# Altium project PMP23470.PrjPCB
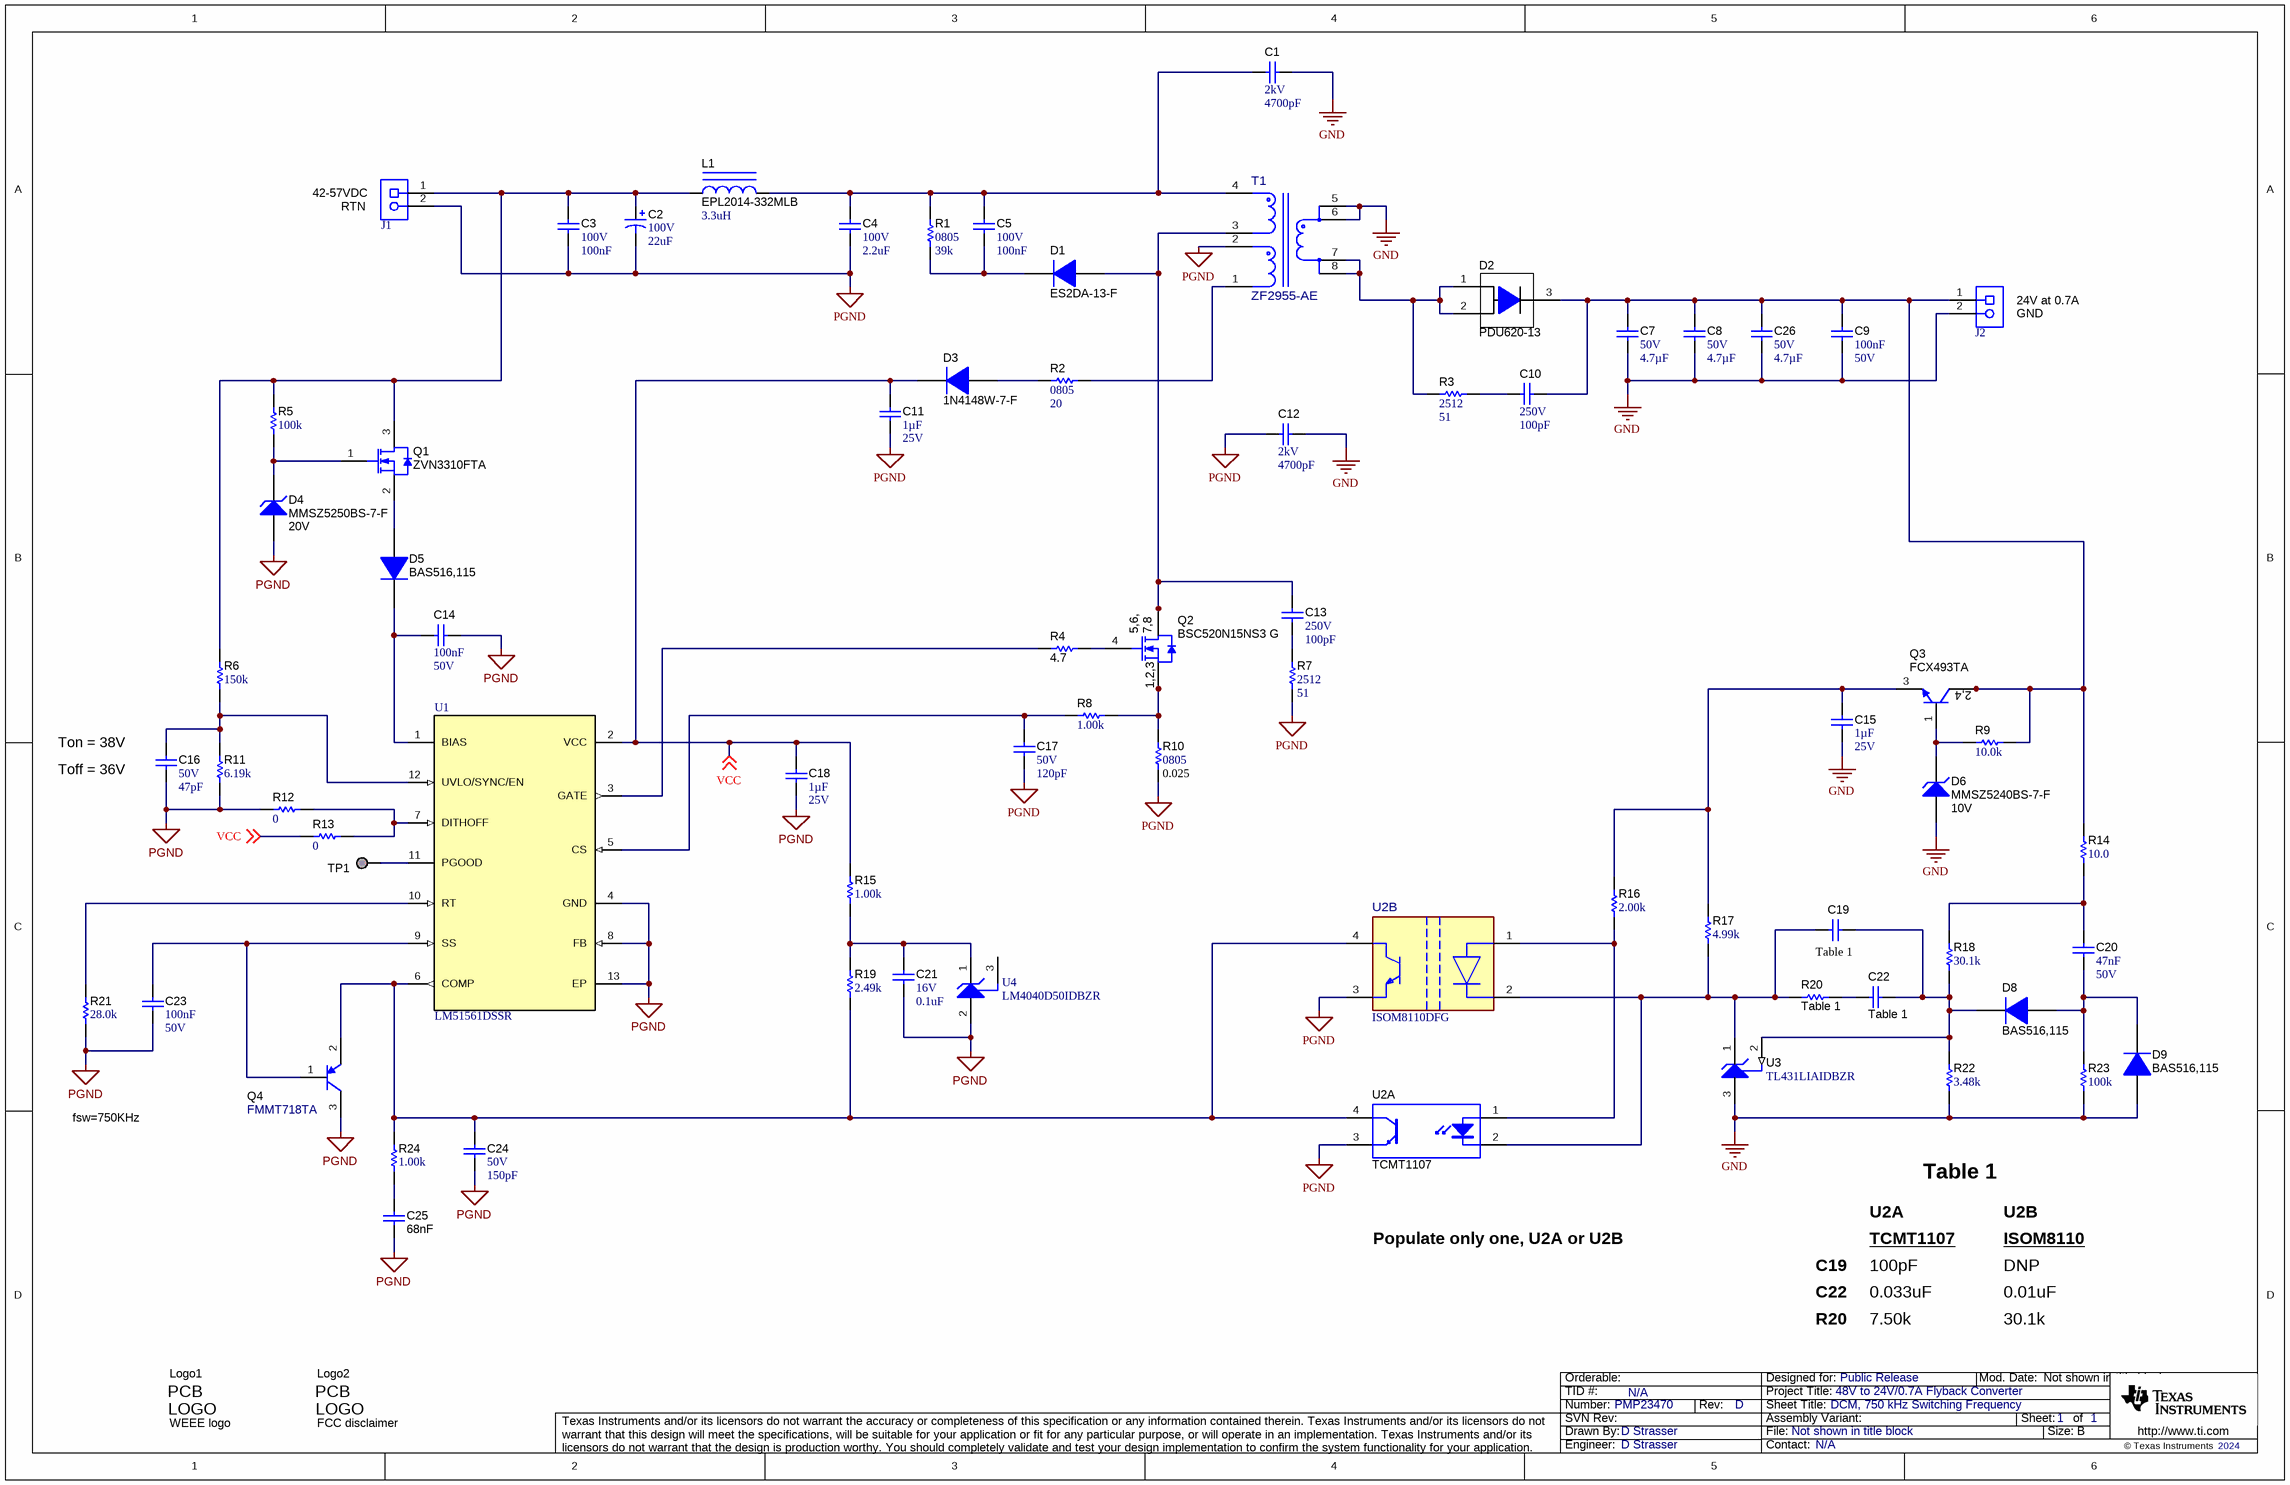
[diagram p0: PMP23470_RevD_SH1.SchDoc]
CopyrightYear: 2024; PCB_Layout: D Strasser; PCB_Rev: D; PRJ_Customer: Public Release; PRJ_Engineer: D Strasser; PRJ_Number: PMP23470; PRJ_Title: 48V to 24V/0.7A Flyback Converter; SCH_Rev: D; TechSupport: N/A; TID: N/A
1 sheet, 73 parts. Net scope: global (net labels, ports and power ports of the same name join across sheets).
Board file: PMP23470_RevD.PcbDoc

## Sheet PMP23470_RevD_SH1.SchDoc: DCM, 750 kHz Switching Frequency
size 431 x 279 mm; Date: Not shown in title block; ApprovedBy: Not shown in title block; CheckedBy: Not shown in title block; Author: Not shown in title block; CompanyName: Not shown in title block; DrawnBy: D Strasser; Engineer: Not shown in title block; Organization: Not shown in title block; Address1: Not shown in title block; Address2: Not shown in title block; Address3: Not shown in title block; Address4: Not shown in title block; DocumentNumber: 1; Revision: Use project parameter SCH_Rev; SheetNumber: 1; SheetTotal: 1; PageSetup: Record=PageOptions¦CenterHorizontal=True¦CenterVertical=True¦PrintScale=1.00¦XCorrection=1.00¦YCorrection=1.00¦PrintKind=0¦BorderSize=5000000¦LeftOffset=0¦BottomOffset=0¦Orientation=2¦PaperLength=1000¦PaperWidth=1000¦Scale=100¦PaperSource=15¦PrintQuality=600¦MediaType=1¦DitherType=10¦PaperKind=Letter¦PrintScaleMode=1

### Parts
C1  VDC_V: 2kV  ValueDisplayed: 4700pF  [1812_HV]  (hidden comment: 1812GC472KA1)
C2  VDC_V: 100V  ValueDisplayed: 22uF  [SM_RADIAL_F]  (hidden comment: EEE-FK2A220P)
C3  VDC_V: 100V  Cap_F: 100nF  [0805_HV1]  (hidden comment: 885012207128)
C4  VDC_V: 100V  ValueDisplayed: 2.2uF  [1210_210L]  (hidden comment: C1210C225K1RAC7800)
C5  VDC_V: 100V  Cap_F: 100nF  [0805_HV1]  (hidden comment: 885012207128)
C7  VDC_V: 50V  ValueDisplayed: 4.7µF  [1210_280]  (hidden comment: C1210C475K5RACAUTO)
C8  VDC_V: 50V  ValueDisplayed: 4.7µF  [1210_280]  (hidden comment: C1210C475K5RACAUTO)
C9  Cap_F: 100nF  VDC_V: 50V  [0603L]  (hidden comment: C0603C104K5RACTU)
C10  VDC_V: 250V  ValueDisplayed: 100pF  [0805_HV1]  (hidden comment: GRM21A5C2E101JW01D)
C11  Cap_F: 1µF  VDC_V: 25V  [0603L]  (hidden comment: C0603C105K3RACTU)
C12  VDC_V: 2kV  ValueDisplayed: 4700pF  [1812_HV]  (hidden comment: 1812GC472KA1)
C13  VDC_V: 250V  ValueDisplayed: 100pF  [0805_HV1]  (hidden comment: GRM21A5C2E101JW01D)
C14  Cap_F: 100nF  VDC_V: 50V  [0603L]  (hidden comment: C0603C104K5RACTU)
C15  Cap_F: 1µF  VDC_V: 25V  [0603L]  (hidden comment: C0603C105K3RACTU)
C16  VDC_V: 50V  ValueDisplayed: 47pF  [0402L]  (hidden comment: 885012005044)
C17  VDC_V: 50V  ValueDisplayed: 120pF  [0402L]  (hidden comment: GRM1555C1H121JA01D)
C18  Cap_F: 1µF  VDC_V: 25V  [0603L]  (hidden comment: C0603C105K3RACTU)
C19  Table 1  [0402L]  (value not drawn)
C20  Cap_F: 47nF  VDC_V: 50V  [0603L]  (hidden comment: C1608X7R1H473K080AA)
C21  VDC_V: 16V  ValueDisplayed: 0.1uF  [0402L]  (hidden comment: 885012205037)
C22  Table 1  [0603L]
C23  Cap_F: 100nF  VDC_V: 50V  [0603L]  (hidden comment: C0603C104K5RACTU)
C24  VDC_V: 50V  ValueDisplayed: 150pF  [0402L]  (hidden comment: 885012005062)
C25  Cap_F: 68nF  [0603L]  (hidden comment: 885012206070)
C26  VDC_V: 50V  ValueDisplayed: 4.7µF  [1210_280]  (hidden comment: C1210C475K5RACAUTO)
D1  ES2DA-13-F  [SMA]
D2  PDU620-13  [POWERDI5]
D3  1N4148W-7-F  [SOD-123]
D4  MMSZ5250BS-7-F  value 20V  [SOD-323]
D5  BAS516,115  [SOD-523]
D6  MMSZ5240BS-7-F  value 10V  [SOD-323]
D8  BAS516,115  [SOD-523]
D9  BAS516,115  [SOD-523]
J1  ED555/2DS  [TERM_BLK_ED555-2DS]  (value not drawn)
J2  ED555/2DS  [TERM_BLK_ED555-2DS]  (value not drawn)
L1  EPL2014-332MLB  ValueDisplayed: 3.3uH  [EPL2014]
Logo1  WEEE logo  [WEEE_Minimum]  (no BOM)
Logo2  FCC disclaimer  [FCC_disclaimer]  (no BOM)
Q1  ZVN3310FTA  [SOT-23]
Q2  BSC520N15NS3 G  [PG-TDSON-8]
Q3  FCX493TA  [SOT-89-3]
Q4  FMMT718TA  [SOT-23L]
R1  PackageReference: 0805  ValueDisplayed: 39k  [0805_HV]  (hidden comment: CRCW080539K0JNEA)
R2  PackageReference: 0805  ValueDisplayed: 20  [0805_HV]  (hidden comment: ERJ-6GEYJ200V)
R3  ValueDisplayed: 51  [2512]  (hidden comment: CRCW251251R0JNEG)
R4  ValueDisplayed: 4.7  [0402L]  (hidden comment: CRCW04024R70JNED)
R5  ValueDisplayed: 100k  [0402L]  (hidden comment: CRCW0402100KFKED)
R6  ValueDisplayed: 150k  [0402L]  (hidden comment: CRCW0402150KFKED)
R7  ValueDisplayed: 51  [2512]  (hidden comment: CRCW251251R0JNEG)
R8  ValueDisplayed: 1.00k  [0402L]  (hidden comment: CRCW04021K00FKED)
R9  ValueDisplayed: 10.0k  [0402L]  (hidden comment: CRCW040210K0FKED)
R10  PackageReference: 0805  ValueDisplayed: 0.025  [WSL0805]  (hidden comment: WSL0805R0250FEA)
R11  ValueDisplayed: 6.19k  [0402L]  (hidden comment: CRCW04026K19FKED)
R12  ValueDisplayed: 0  [0402L]  (hidden comment: CRCW04020000Z0ED)
R13  ValueDisplayed: 0  [0402L]  (hidden comment: CRCW04020000Z0ED)
R14  ValueDisplayed: 10.0  [0402L]  (hidden comment: CRCW040210R0FKED)
R15  ValueDisplayed: 1.00k  [0402L]  (hidden comment: CRCW04021K00FKED)
R16  ValueDisplayed: 2.00k  [0402L]  (hidden comment: CRCW04022K00FKED)
R17  ValueDisplayed: 4.99k  [0402L]  (hidden comment: CRCW04024K99FKED)
R18  ValueDisplayed: 30.1k  [0402L]  (hidden comment: CRCW040230K1FKED)
R19  ValueDisplayed: 2.49k  [0402L]  (hidden comment: CRCW04022K49FKED)
R20  Table 1  [0402L]
R21  ValueDisplayed: 28.0k  [0402L]  (hidden comment: CRCW040228K0FKED)
R22  ValueDisplayed: 3.48k  [0402L]  (hidden comment: CRCW04023K48FKED)
R23  ValueDisplayed: 100k  [0402L]  (hidden comment: CRCW0402100KFKED)
R24  ValueDisplayed: 1.00k  [0402L]  (hidden comment: CRCW04021K00FKED)
T1  ZF2955-AE  [FP-ZF2955-AE_SMT_XFRMR_13MM2_10MM9-MFG]
TP1  TP_SM_1MM  [TP_SM_1MM]  (value not drawn)  (no BOM)
U1  LM51561DSSR  [DSS0012B]
U2A  TCMT1107  [SOP-4]
U2B  ISOM8110DFG  [DFG0004A-MFG]
U3  TL431LIAIDBZR  [DBZ0003A_L]
U4  LM4040D50IDBZR  [DBZ0003A_N]

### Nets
GND: C1.1 C7.1 C8.1 C9.2 C12.1 C15.1 C26.1 D6.2(A) D9.2(A) J2.2 R22.2 R23.2 T1.5 T1.6 U3.3(ANODE)
PGND: C2.2(-) C3.1 C4.1 C11.1 C12.2 C14.1 C16.1 C17.1 C18.1 C21.2 C23.2 C24.2 C25.1 D4.2(A) J1.2 Q4.3(C) R7.2 R10.2 R11.2 R12.1 R21.2 T1.2 U1.4(GND) U1.8(FB) U1.13(EP) U2A.3(E) U2B.3(Emitter) U4.2(ANODE)
VCC: C11.2 C18.2 D3.1(K) R13.1 R15.1 U1.2(VCC) ; off-sheet VCC
NetC1_2: C1.2 C4.2 C5.2 L1.2 R1.1 T1.4
NetC2_1: C2.1(+) C3.2 J1.1 L1.1 Q1.3(D) R5.1 R6.1
NetC5_1: C5.1 D1.1(K) R1.2
NetC7_2: C7.2 C8.2 C9.1 C10.2 C26.2 D2.3(K) J2.1 Q3.2(C) Q3.4(C) R9.2 R14.1
NetC10_1: C10.1 R3.2
NetC13_1: C13.1 R7.1
NetC13_2: C13.2 D1.2(A) Q2.5(D) Q2.6(D) Q2.7(D) Q2.8(D) Q2.9(D) T1.3
NetC14_2: C14.2 D5.1(K) U1.1(BIAS)
NetC15_2: C15.2 Q3.3(E) R16.1 R17.1
NetC16_2: C16.2 R6.2 R11.1 U1.12(UVLO/SYNC/EN)
NetC17_2: C17.2 R8.2 U1.5(CS)
NetC19_1: C19.1 C22.1 D8.1(K) R18.2 R22.1 U3.2(REF)
NetC19_2: C19.2 R17.2 R20.1 U2A.2(K) U2B.2(CAT) U3.1(CATHODE)
NetC20_1: C20.1 D8.2(A) D9.1(K) R23.1
NetC20_2: C20.2 R14.2 R18.1
NetC21_1: C21.1 R15.2 R19.1 U4.1(CATHODE)
NetC22_2: C22.2 R20.2
NetC23_1: C23.1 Q4.1(B) U1.9(SS)
NetC24_1: C24.1 Q4.2(E) R19.2 R24.1 U1.6(COMP) U2A.4(C) U2B.4(Collector)
NetC25_2: C25.2 R24.2
NetD2_1: D2.1(A) D2.2(A) R3.1 T1.7 T1.8
NetD3_2: D3.2(A) R2.1
NetD4_1: D4.1(K) Q1.1(G) R5.2
NetD5_2: D5.2(A) Q1.2(S)
NetD6_1: D6.1(K) Q3.1(B) R9.1
NetQ2_1: Q2.1(S) Q2.2(S) Q2.3(S) R8.1 R10.1
NetQ2_4: Q2.4(G) R4.1
NetR2_2: R2.2 T1.1
NetR4_2: R4.2 U1.3(GATE)
NetR12_2: R12.2 R13.2 U1.7(DITHOFF)
NetR16_2: R16.2 U2A.1(A) U2B.1(AN)
NetR21_1: R21.1 U1.10(RT)
NetTP1_1: TP1.1 U1.11(PGOOD)

Not connected (* = marked no-connect by the designer): U4 3(NC)

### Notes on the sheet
- (near J1) 42-57VDC
- (near J1) RTN
- (near J2) 24V at 0.7A
- (near J2) GND
- (near C16) Ton = 38V
- (near C16) Toff = 36V
- (near C19) Table 1
- fsw=750KHz
- Table 1
- Populate only one, U2A or U2B
- TCMT1107
- U2A
- ISOM8110
- U2B
- C19
- C22
- 100pF
- 0.033uF
- DNP
- 0.01uF
- R20
- 7.50k
- 30.1k

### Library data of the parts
C1 C12 = CMP-0009294-2: CAP, CERM, 4700 pF, 2000 V, +/- 10%, X7R, 1812; Manufacturer: AVX; TaMin_C: -55°C; Polarized: N; SizeAreaWB_mm2: 23.1; Value1: Unknown; U/M: EA; Value: 4700pF; TaMax_C: 125°C; SizeZ_mm: 1.35; SizeX_mm: 4.5; SizeY_mm: 3.2; Cap_Case: 1812; Value2: 2000V; SizeArea_mm2: 14.4; Cap_F: 4.7nF; AEC Category: Q200
C2 = CMP-0011202-2: CAP, AL, 22 uF, 100 V, +/- 20%, 1.3 ohm, AEC-Q200 Grade 2, SMD; Manufacturer: Panasonic; TaMin_C: -55°C; ESR_ohm: 1.3; Polarized: Y; SizeAreaWB_mm2: 123.6; Value1: 1.3 ohm; U/M: EA; Value: 22uF; TaMax_C: 105°C; SizeZ_mm: 10.2; SizeX_mm: 10; SizeY_mm: 8.3; Cap_Case: F; SizeArea_mm2: 83; CompType: Capacitor; Cap_F: 22µF; IRMS_A: 130mA; AEC Grade: 2; AEC Category: Q200
C3 C5 = CMP-0750058-1: CAP, CERM, 0.1 µF, 100 V,+/- 10%, X7R, 0805; Manufacturer: Wurth Elektronik; TaMin_C: -55°C; AEC Category: Q200; U/M: EA; SizeY_mm: 1.25; Polarized: N; Value: 0.1uF; SizeX_mm: 2; TaMax_C: 125°C; ValueDisplayed: 0.1µF; SizeArea_mm2: 2.5; Cap_Case: 0805; SizeZ_mm: 1.45; SizeAreaWB_mm2: 6.75
C4 = CMP-0009084-2: CAP, CERM, 2.2 uF, 100 V, +/- 10%, X7R, 1210; Manufacturer: Kemet; TaMin_C: -55°C; Polarized: N; SizeAreaWB_mm2: 14.7; Value1: Unknown; U/M: EA; Value: 2.2uF; TaMax_C: 125°C; SizeZ_mm: 2.1; SizeX_mm: 3.2; SizeY_mm: 2.5; Cap_Case: 1210; SizeArea_mm2: 8; Cap_F: 2.2µF; AEC Category: Q200
C7 C8 C26 = CMP-0079604-1: CAP, CERM, 4.7 µF, 50 V,+/- 10%, X7R, AEC-Q200 Grade 1, 1210; Manufacturer: Kemet; TaMin_C: -55°C; Polarized: N; SizeAreaWB_mm2: 14.7; U/M: EA; Value: 4.7uF; TaMax_C: 125°C; SizeZ_mm: 2.8; SizeX_mm: 3.2; SizeY_mm: 2.5; Cap_Case: 1210; SizeArea_mm2: 8; AEC Qualified: Y; AEC Grade: 1; AEC Category: Q200
C9 C14 C23 = CMP-0006861-4: CAP, CERM, 0.1 uF, 50 V, +/- 10%, X7R, 0603; Manufacturer: Kemet; TaMin_C: -55°C; Polarized: N; SizeAreaWB_mm2: 4.68; Value1: Unknown; U/M: EA; Value: 0.1uF; TaMax_C: 125°C; SizeZ_mm: 1; SizeX_mm: 1.6; SizeY_mm: 0.8; Cap_Case: 0603; SizeArea_mm2: 1.28; AEC Category: Q200
C10 C13 = CMP-0008236-2: CAP, CERM, 100 pF, 250 V, +/- 5%, C0G/NP0, 0805; Manufacturer: MuRata; TaMin_C: -55°C; Polarized: N; SizeAreaWB_mm2: 6.75; Value1: Unknown; U/M: EA; Value: 100pF; TaMax_C: 125°C; SizeZ_mm: 1.45; SizeX_mm: 2; SizeY_mm: 1.25; Cap_Case: 0805; SizeArea_mm2: 2.5; AEC Category: Q200
C11 C15 C18 = CMP-0006867-4: CAP, CERM, 1 uF, 25 V, +/- 10%, X7R, 0603; Manufacturer: Kemet; TaMin_C: -55°C; Polarized: N; SizeAreaWB_mm2: 4.68; Value1: Unknown; U/M: EA; Value: 1uF; TaMax_C: 125°C; SizeZ_mm: 1; SizeX_mm: 1.6; SizeY_mm: 0.8; Cap_Case: 0603; SizeArea_mm2: 1.28; AEC Category: Q200
C16 = CMP-0006214-2: CAP, CERM, 47 pF, 50 V, +/- 5%, C0G/NP0, 0402; Manufacturer: Wurth Elektronik; TaMin_C: -55°C; Polarized: N; SizeAreaWB_mm2: 3; Value1: Unknown; U/M: EA; Value: 47pF; TaMax_C: 125°C; SizeZ_mm: 0.6; SizeX_mm: 1; SizeY_mm: 0.5; Cap_Case: 0402; AEC Category: Q200
C17 = CMP-0006417-2: CAP, CERM, 120 pF, 50 V, +/- 5%, C0G/NP0, 0402; Manufacturer: MuRata; TaMin_C: -55°C; Polarized: N; SizeAreaWB_mm2: 3; Value1: Unknown; U/M: EA; Value: 120pF; TaMax_C: 125°C; SizeZ_mm: 0.6; SizeX_mm: 1; SizeY_mm: 0.5; Cap_Case: 0402; AEC Category: Q200
C19 = CMP-0006217-2: CAP, CERM, 100 pF, 50 V, +/- 5%, C0G/NP0, 0402; Manufacturer: Wurth Elektronik; PartNumber: 885012005061; TaMin_C: -55°C; Polarized: N; SizeAreaWB_mm2: 3; Value1: Unknown; U/M: EA; Value: 100pF; TaMax_C: 125°C; SizeZ_mm: 0.6; SizeX_mm: 1; SizeY_mm: 0.5; Cap_Case: 0402; Value2: 50V; AEC Category: Q200
C20 = CMP-0007049-4: CAP, CERM, 0.047 uF, 50 V, +/- 10%, X7R, 0603; Manufacturer: TDK; TaMin_C: -55°C; ESR_ohm: 49.007m; Polarized: N; SizeAreaWB_mm2: 4.68; Value1: 0.049007 ohm; U/M: EA; TaMax_C: 125°C; SizeZ_mm: 1; SizeX_mm: 1.6; SizeY_mm: 0.8; Cap_Case: 0603; SizeArea_mm2: 1.28; IRMS_A: 767.528mA; AEC Category: Q200
C21 = CMP-0006228-2: CAP, CERM, 0.1 uF, 16 V, +/- 10%, X7R, 0402; Manufacturer: Wurth Elektronik; TaMin_C: -55°C; Polarized: N; SizeAreaWB_mm2: 3; Value1: Unknown; U/M: EA; Value: 0.1uF; TaMax_C: 125°C; SizeZ_mm: 0.6; SizeX_mm: 1; SizeY_mm: 0.5; Cap_Case: 0402; Cap_F: 100nF; AEC Category: Q200
C22 = CMP-0750039-1: CAP, CERM, 0.01 µF, 50 V,+/- 10%, X7R, 0603; Manufacturer: Wurth Elektronik; PartNumber: 885012206089; Polarized: N; AEC Category: Q200; TaMax_C: 125°C; SizeAreaWB_mm2: 4.68; Value: 0.01uF; SizeArea_mm2: 1.28; SizeY_mm: 0.8; SizeZ_mm: 1; ValueDisplayed: 0.01µF; SizeX_mm: 1.6; VDC_V: 50V; U/M: EA; Cap_Case: 0603; Cap_F: 10nF; TaMin_C: -55°C
C24 = CMP-0064913-2: CAP, CERM, 150 pF, 50 V,+/- 5%, C0G/NP0, 0402; Manufacturer: Wurth Elektronik; TaMin_C: -55°C; Polarized: N; SizeAreaWB_mm2: 3; Value1: Unknown; U/M: EA; Value: 150pF; TaMax_C: 125°C; SizeZ_mm: 0.6; SizeX_mm: 1; SizeY_mm: 0.5; Cap_Case: 0402; AEC Category: Q200
C25 = CMP-0750069-1: CAP, CERM, 0.068 µF, 25 V,+/- 10%, X7R, 0603; Manufacturer: Wurth Elektronik; SizeAreaWB_mm2: 4.68; Cap_Case: 0603; U/M: EA; SizeArea_mm2: 1.28; TaMin_C: -55°C; Value: 0.068uF; SizeY_mm: 0.8; SizeX_mm: 1.6; AEC Category: Q200; VDC_V: 25V; AEC Qualified: N; SizeZ_mm: 1; TaMax_C: 125°C
D1 = CMP-0076892-2: Diode, Superfast Rectifier, 200 V, 2 A, SMA; Manufacturer: Diodes Inc.; Vf_V: 920mV; SizeY_mm: 2.92; RJC_CperW: 20.0; Value: 200V; SizeX_mm: 5.59; Value1: 2A; Value2: 0.92V; AEC Category: Q101; SizeAreaWB_mm2: 37.3428; Green_REACh: Incomplete; SizeArea_mm2: 16.3228; SizeZ_mm: 2.87; Green_Lifecycle: Not Set; TJmax_C: 150°C
D2 = CMP-0077019-2: Diode, Ultrafast, 200 V, 6 A, PowerDI5; Manufacturer: Diodes Inc.; SizeY_mm: 3.9; Value1: 6A; SizeArea_mm2: 24.96; SizeZ_mm: 1.05; Vf_V: 940mV; SizeX_mm: 6.4; Value2: 0.94V; Value: 200V; SizeAreaWB_mm2: 49.56; TJmax_C: 175°C; AEC Category: Q101; Green_Lifecycle: Not Set; Green_REACh: Incomplete
D3 = CMP-0029001-2: Diode, Ultrafast, 100 V, 0.15 A, SOD-123; Manufacturer: Diodes Inc.; SizeX_mm: 3.85; Value2: 1.25V; Green_REACh: Passed; TJmax_C: 150°C; AEC Category: Q101; SizeAreaWB_mm2: 13.095; Value: 100V; Green_Lifecycle: Active; SizeY_mm: 1.7; Value1: 0.15A; SizeArea_mm2: 6.545; Io_A: 150mA; SizeZ_mm: 1.35
D4 = CMP-0005836-4: Diode, Zener, 20 V, 200 mW, SOD-323; Manufacturer: Diodes Inc.; Value1: 0.2W; SizeX_mm: 2.7; SizeArea_mm2: 3.645; AEC Category: Q101; SizeAreaWB_mm2: 8.695; Power_W: 200mW; RJA_CperW: 350; SizeZ_mm: 1; SizeY_mm: 1.35
D5 D8 D9 = CMP-0076979-3: Diode, Switching, 100 V, 0.25 A, SOD-523; Manufacturer: Nexperia; Value: 100V; SizeAreaWB_mm2: 5.13; Vf_V: 1.25V; SizeArea_mm2: 1.53; SizeY_mm: 0.9; Green_Lifecycle: Not Set; AEC Category: Q101; SizeX_mm: 1.7; Green_REACh: Incomplete; Io_A: 250mA; TJmax_C: 150°C; SizeZ_mm: 0.65; Value1: 0.25A
D6 = CMP-0005829-3: Diode, Zener, 10 V, 200 mW, SOD-323; Manufacturer: Diodes Inc.; SizeZ_mm: 1; Value1: 0.2W; SizeAreaWB_mm2: 8.695; SizeArea_mm2: 3.645; SizeY_mm: 1.35; SizeX_mm: 2.7; AEC Category: Q101; Power_W: 200mW; RJA_CperW: 350
J1 J2 = CMP-0074913-1: Terminal Block, 3.5mm Pitch, 2x1, TH; Manufacturer: On-Shore Technology; Cert_VDE: Y; CNHeader: False; Current_A: 6A; Green_Lifecycle: Active; Shrouded: N; Gender: Female; Green_REACh: Passed; Voltage_V: 150V; Row_Count: 1; Pitch_mm: 3.5; ContactFinish: Brass; CT: True
L1 = CMP-0060326-1: Inductor, Shielded, Ferrite, 3.3 uH, 1.1 A, 0.15 ohm, SMD; Manufacturer: Coilcraft; Isat: 1.1A @ 30% inductance drop; Irms: 1.23A @ 40C rise; Green_Lifecycle: Not Set; SizeAreaWB_mm2: 9; DCR_ohm: 0.15; Green_REACh: Incomplete; Value: 3.3uH; Imax_A: 1.1A; SizeZ_mm: 1.4; SizeX_mm: 2; SizeArea_mm2: 4; Ind_H: 3.3µH; AEC Category: Q200
Logo1 = CMP-0074769-4: Manufacturer: Texas Instruments; CompType: IC; AEC Category: Q200
Logo2 = CMP-0074847-1: FCC_disclaimer
Q1 = CMP-0001039-3: MOSFET, N-CH, 100 V, 0.1 A, SOT-23; Alternate Manufacturer: None; Manufacturer: Diodes Inc.; SizeZ_mm: 1.1; ChType: N; VdsMax_V: 100V; SizeX_mm: 2.5; SizeY_mm: 3; Vgs_V: 20V; Value: 100V; SizeArea_mm2: 7.5; AEC Category: Q101; IdsMax_A: 100mA; SizeAreaWB_mm2: 14; U/M: EA
Q2 = CMP-0001049-2: MOSFET, N-CH, 150 V, 21 A, PG-TDSON-8; Alternate Manufacturer: None; Manufacturer: Infineon Technologies; SizeZ_mm: 1.12; ChType: N; Value2: 8.7 nC; VdsMax_V: 150V; SizeX_mm: 5.99; SizeY_mm: 4.9; Vgs_V: 20V; Value: 150V; SizeArea_mm2: 29.351; AEC Category: Q101; IdsMax_A: 21A; SizeAreaWB_mm2: 55.131; U/M: EA; QgTyp_nC: 8.7
Q3 = CMP-0000415-2: Transistor, NPN, 100 V, 1 A, SOT-89; Manufacturer: Diodes Inc.; TaMax_C: 150°C; Value2: 300; Value1: 1 A; Vcesat1_V: 600mV; SizeX_mm: 4.1; SizeY_mm: 4.5; TaMin_C: -65°C; IcRated_A: 1A; CompType: BJT; SizeZ_mm: 1.5; Value: 100 V; SizeArea_mm2: 18.45; NPN: 1; Vceo_V: 100V; PNP: 0; AEC Category: Q101; SizeAreaWB_mm2: 28.05; U/M: EA
Q4 = CMP-0000330-2: Transistor, PNP, 20 V, 1.5 A, SOT-23; Manufacturer: Diodes Inc.; TaMax_C: 150°C; Value2: 6; Value1: 1.5 A; Vcesat1_V: 20V; SizeX_mm: 2.5; SizeY_mm: 3; TaMin_C: -55°C; IcRated_A: 1.5A; CompType: BJT; SizeZ_mm: 1.1; Value: 20 V; SizeArea_mm2: 7.5; NPN: 0; PNP: 1; AEC Category: Q101; SizeAreaWB_mm2: 14; U/M: EA
R1 = CMP-0020536-3: RES, 39 k, 5%, 0.125 W, AEC-Q200 Grade 0, 0805; Manufacturer: Vishay-Dale; Power_W: 125mW; TempCo: 200 ppm/C; Value_Code: 39k0; Value: 39k; EIA_Code: E24; SizeX_mm: 2; SizeY_mm: 1.25; SizeZ_mm: 1.45; Value2: 0.125W; SizeArea_mm2: 2.5; AEC Qualified: Y; VDC_V: 150V; AEC Category: Q200; AEC Grade: 0
R2 = CMP-0020668-3: RES, 20, 5%, 0.125 W, AEC-Q200 Grade 0, 0805; Manufacturer: Panasonic; Power_W: 125mW; TempCo: 200 ppm/C; Value_Code: 20R0; Value: 20; EIA_Code: E24; SizeX_mm: 2; SizeY_mm: 1.25; SizeZ_mm: 1.45; Value2: 0.125W; SizeArea_mm2: 2.5; AEC Qualified: Y; VDC_V: 150V; AEC Category: Q200; AEC Grade: 0; SizeAreaWB_mm2: 6.75
R3 R7 = CMP-0015978-3: RES, 51, 5%, 1 W, AEC-Q200 Grade 0, 2512; Manufacturer: Vishay-Dale; Power_W: 1W; TempCo: 200 ppm/C; Value_Code: 51R0; Value: 51; EIA_Code: E24; SizeX_mm: 6.3; SizeY_mm: 3.2; SizeZ_mm: 0.71; SizeArea_mm2: 20.16; AEC Qualified: Y; VDC_V: 500V; AEC Grade: 0; AEC Category: Q200
R4 = CRCW04024R70JNED: RES, 4.7, 5%, 0.063 W, 0402; Manufacturer: Vishay-Dale; CompType: Resistor; Value: 4.7; Value_Code: 4R70; Tolerance_%: 5; Power_W: 0.063; Value2: 0.063W; VDC_V: 50; TempCo: 200 ppm/C; EIA_Code: E24; U/M: EA
R5 R23 = CMP-0025950-3: RES, 100 k, 1%, 0.063 W, AEC-Q200 Grade 0, 0402; Manufacturer: Vishay-Dale; Power_W: 63mW; TempCo: 100 ppm/C; Value: 100k; EIA_Code: E96; SizeX_mm: 1; SizeY_mm: 0.5; SizeZ_mm: 0.6; Value2: 0.063W; AEC Qualified: Y; VDC_V: 50V; AEC Category: Q200; AEC Grade: 0
R6 = CMP-0026021-3: RES, 150 k, 1%, 0.063 W, AEC-Q200 Grade 0, 0402; Manufacturer: Vishay-Dale; Power_W: 63mW; TempCo: 100 ppm/C; Value: 150k; EIA_Code: E96; SizeX_mm: 1; SizeY_mm: 0.5; SizeZ_mm: 0.6; Value2: 0.063W; AEC Qualified: Y; VDC_V: 50V; AEC Category: Q200; AEC Grade: 0
R8 R15 R24 = CMP-0026071-3: RES, 1.00 k, 1%, 0.063 W, AEC-Q200 Grade 0, 0402; Manufacturer: Vishay-Dale; Power_W: 63mW; TempCo: 100 ppm/C; Value_Code: 1k00; Value: 1.00k; EIA_Code: E96; Res_ohm: 1k; SizeX_mm: 1; SizeY_mm: 0.5; SizeZ_mm: 0.6; Value2: 0.063W; AEC Qualified: Y; VDC_V: 50V; AEC Category: Q200; AEC Grade: 0
R9 = CMP-0025958-3: RES, 10.0 k, 1%, 0.063 W, AEC-Q200 Grade 0, 0402; Manufacturer: Vishay-Dale; Power_W: 63mW; TempCo: 100 ppm/C; Value_Code: 10k0; Value: 10.0k; EIA_Code: E96; Res_ohm: 10k; SizeX_mm: 1; SizeY_mm: 0.5; SizeZ_mm: 0.6; Value2: 0.063W; AEC Qualified: Y; VDC_V: 50V; AEC Category: Q200; AEC Grade: 0
R10 = CMP-0021981-2: RES, 0.025, 1%, 0.25 W, 0805; Manufacturer: Vishay-Dale; Power_W: 250mW; TempCo: 75 ppm/C; Value_Code: R025; U/M: EA; Value: 0.025; EIA_Code: E96; Res_ohm: 25m; SizeX_mm: 2.03; SizeY_mm: 1.27; SizeZ_mm: 0.584; Value2: 0.25W; SizeArea_mm2: 2.5781; AEC Category: Q200
R11 = CMP-0026513-2: RES, 6.19 k, 1%, 0.063 W, AEC-Q200 Grade 0, 0402; Manufacturer: Vishay-Dale; Power_W: 63mW; TempCo: 100 ppm/C; Value_Code: 6k19; Value: 6.19k; EIA_Code: E96; SizeX_mm: 1; SizeY_mm: 0.5; SizeZ_mm: 0.6; Value2: 0.063W; AEC Qualified: Y; VDC_V: 50V; AEC Category: Q200; AEC Grade: 0
R12 R13 = CMP-0026822-3: RES, 0, 5%, 0.063 W, AEC-Q200 Grade 0, 0402; Manufacturer: Vishay-Dale; Power_W: 63mW; TempCo: 200 ppm/C; Value_Code: 0000; Value: 0; EIA_Code: E24; SizeX_mm: 1; SizeY_mm: 0.5; SizeZ_mm: 0.6; Value2: 0.063W; AEC Qualified: Y; VDC_V: 50V; AEC Category: Q200
R14 = CMP-0025963-3: RES, 10.0, 1%, 0.063 W, AEC-Q200 Grade 0, 0402; Manufacturer: Vishay-Dale; Power_W: 63mW; TempCo: 100 ppm/C; Value_Code: 10R0; Value: 10.0; EIA_Code: E96; Res_ohm: 10; SizeX_mm: 1; SizeY_mm: 0.5; SizeZ_mm: 0.6; Value2: 0.063W; AEC Qualified: Y; VDC_V: 50V; AEC Category: Q200; AEC Grade: 0
R16 = CMP-0026227-2: RES, 2.00 k, 1%, 0.063 W, AEC-Q200 Grade 0, 0402; Manufacturer: Vishay-Dale; Power_W: 63mW; TempCo: 100 ppm/C; Value_Code: 2k00; Value: 2.00k; EIA_Code: E96; Res_ohm: 2k; SizeX_mm: 1; SizeY_mm: 0.5; SizeZ_mm: 0.6; Value2: 0.063W; AEC Qualified: Y; VDC_V: 50V; AEC Category: Q200; AEC Grade: 0
R17 = CMP-0026414-2: RES, 4.99 k, 1%, 0.063 W, AEC-Q200 Grade 0, 0402; Manufacturer: Vishay-Dale; Power_W: 63mW; TempCo: 100 ppm/C; Value_Code: 4k99; Value: 4.99k; EIA_Code: E96; SizeX_mm: 1; SizeY_mm: 0.5; SizeZ_mm: 0.6; Value2: 0.063W; AEC Qualified: Y; VDC_V: 50V; AEC Category: Q200; AEC Grade: 0
R18 = CMP-0026284-2: RES, 30.1 k, 1%, 0.063 W, AEC-Q200 Grade 0, 0402; Manufacturer: Vishay-Dale; Power_W: 63mW; TempCo: 100 ppm/C; Value_Code: 30k1; Value: 30.1k; EIA_Code: E96; SizeX_mm: 1; SizeY_mm: 0.5; SizeZ_mm: 0.6; Value2: 0.063W; AEC Qualified: Y; VDC_V: 50V; AEC Category: Q200; AEC Grade: 0
R19 = CMP-0026237-2: RES, 2.49 k, 1%, 0.063 W, AEC-Q200 Grade 0, 0402; Manufacturer: Vishay-Dale; Power_W: 63mW; TempCo: 100 ppm/C; Value_Code: 2k49; Value: 2.49k; EIA_Code: E96; SizeX_mm: 1; SizeY_mm: 0.5; SizeZ_mm: 0.6; Value2: 0.063W; AEC Qualified: Y; VDC_V: 50V; AEC Category: Q200; AEC Grade: 0
R20 = CMP-0026284-2: RES, 30.1 k, 1%, 0.063 W, AEC-Q200 Grade 0, 0402; Manufacturer: Vishay-Dale; PartNumber: CRCW040230K1FKED; Power_W: 63mW; TempCo: 100 ppm/C; Value_Code: 30k1; Value: 30.1k; EIA_Code: E96; SizeX_mm: 1; SizeY_mm: 0.5; SizeZ_mm: 0.6; Value2: 0.063W; AEC Qualified: Y; VDC_V: 50V; AEC Category: Q200; AEC Grade: 0
R21 = CMP-0026219-2: RES, 28.0 k, 1%, 0.063 W, AEC-Q200 Grade 0, 0402; Manufacturer: Vishay-Dale; Power_W: 63mW; TempCo: 100 ppm/C; Value_Code: 28k0; Value: 28.0k; EIA_Code: E96; Res_ohm: 28k; SizeX_mm: 1; SizeY_mm: 0.5; SizeZ_mm: 0.6; Value2: 0.063W; AEC Qualified: Y; VDC_V: 50V; AEC Category: Q200; AEC Grade: 0
R22 = CMP-0026335-2: RES, 3.48 k, 1%, 0.063 W, AEC-Q200 Grade 0, 0402; Manufacturer: Vishay-Dale; Power_W: 63mW; TempCo: 100 ppm/C; Value_Code: 3k48; Value: 3.48k; EIA_Code: E96; SizeX_mm: 1; SizeY_mm: 0.5; SizeZ_mm: 0.6; Value2: 0.063W; AEC Qualified: Y; VDC_V: 50V; AEC Category: Q200; AEC Grade: 0
T1 = CMP-0121891-1: Flyback Transformer, EP7 8pin SMD 40-57Vin, 750kHz, Output 24V/0.7A, 11.6V/0.02A, Turns Ratio 1:1:0.5; Manufacturer: Coilcraft; Ind_H: 5.85µH; SizeZ_mm: 9mm; AEC Qualified: No; Voltage_Isolation_Vrms: 1500Vrms
TP1 = CMP-0003825-1: 1mm Test Point, SMT; Manufacturer: Any
U1 = CMP-0860748-1: 2.2-MHz Wide VIN 65-V Non-synchronous Boost/SEPIC/Flyback Controller with Dual Random Spread Spectrum, DSS0012B (WSON-12); Manufacturer: Texas Instruments; Alternate PartNumber: LM51561DSST; SizeX_mm: 2; AEC Qualified: N; SizeZ_mm: 0.8; CompType: IC; SizeY_mm: 3; SizeAreaWB_mm2: 12; SizeArea_mm2: 6; AEC Category: Q200
U2A = CMP-0006166-3: Optocoupler, 3.75 kV, 80-160% CTR, SMT; Manufacturer: Vishay-Semiconductor; CTR (Max): 160%; SizeAreaWB_mm2: 43.65; CTR (Min): 80%; SizeZ_mm: 2.3; SizeX_mm: 7; SizeY_mm: 2.85; SizeArea_mm2: 19.95; Voltage_Isolation_Vrms: 3.75kV
U2B = CMP-0098363-1: 3.75-kVRMS, Single-Channel Opto-Emulator with Transistor Output; Manufacturer: Texas Instruments; SizeZ_mm: 2.65mm; AEC Qualified: No; CTR (Max): 160%; CTR (Min): 80%; Emiiter Collector Voltage: 7V; Forward Current: 10mA; Power_TotalModule: 200mW; Standoff Height: 0.05mm; TaMax_C: +125°C; TaMin_C: -55°C; TJmax_C: +150°C; Turn Off Delay Time: 5us; Turn On Delay Time: 1.7us; Value: 80V; Vf_V: 1.1V; Voltage_Isolation_Vrms: 3750Vrms
U3 = CMP-0084729-1: Programmable Shunt Regulator with Optimized Reference Current, DBZ0003A (SOT-23-3); Manufacturer: Texas Instruments; SizeY_mm: 3; SizeZ_mm: 1.12; SizeX_mm: 2.5; SizeAreaWB_mm2: 14; CompType: IC; AEC Qualified: N; AEC Category: Q200; SizeArea_mm2: 7.5
U4 = CMP-0033034-1: Precision Micropower Shunt Voltage Reference, 1% accuracy, 5 V, 15 ppm / degC, 15 mA, -40 to 85 degC, 3-pin SOT-23 (DBZ), Green (RoHS & no Sb/Br); Manufacturer: Texas Instruments; Rating: Catalog; Initial Accuracy @ 25/deg C(%): 1; Min Iz for Regulation(uA): 79; Temp Coeff(Typ)(ppm/ degree C): 15; VO(V): 5; Temp Coeff(Max)(ppm/ degree C): 150

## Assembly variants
001: not fitted C19 C25 R12 R24 U2A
